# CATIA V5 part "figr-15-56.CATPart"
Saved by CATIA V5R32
Part number: Part1
Bounding box of the stored display mesh (mm): x -75 to -29.087, y -20 to 20, z 0 to 62.461
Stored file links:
  D:\PROJECTS\Project 2022\CATIA V5 6R 2022\Resources\Part Files\c15_catia_v5_6r2022_prt\figr-15-56.CATPart
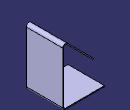
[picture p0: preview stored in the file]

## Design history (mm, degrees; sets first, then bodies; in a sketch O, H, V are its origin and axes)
SheetMetalParameters1: Thickness 1, BendRadius 2, KFactor 0.400515 {= log(min(100,max(20*SheetMetalParameters1.BendRadius,SheetMetalParameters1.Thickness)/SheetMetalParameters1.Thickness))/log(100)/2}, ReliefRadialLength 1, ReliefAxialLength 2, MinimumBendRadius 0
Body1 (main body)
  Sketch1 on xy-plane, origin (0, 0, 0), H (1, 0, 0), V (0, 1, 0)
    line L1 (-75, 20) -> (75, 20)
    line L2 (75, 20) -> (75, -20)
    line L3 (75, -20) -> (-75, -20)
    line L4 (-75, -20) -> (-75, 20)
    distance L1 L3 = 40
    distance L2 L4 = 150
    distance V L2 = 75
    distance H L3 = 20
    horizontal: L1 H, L3 H
    vertical: L2 V, L4 V
  Wall1: Thickness 1, Profile Sketch1
  Sketch2 on face of Wall1, origin (0, 0, 1), H (1, 0, 0), V (0, 1, 0)
    line L1 (-30.2021, 19.5432) -> (-30.2021, -20.6466)
    line L2 (31.0296, 19.5432) -> (31.0296, -20.6466)
    vertical: L1 V, L2 V
  FlatBend1: FlatBendAngle 90, FlatBendAngle 45, Axis Sketch2, FixedPoint vertex [face of Wall1 | face of Wall1 | face of Wall1], FlatBendKFactor 0.400515 {= log(min(100,max(20*FlatBend1.FlatBendRadius,SheetMetalParameters1.Thickness)/SheetMetalParameters1.Thickness))/log(100)/2}, FlatBendKFactor 0.400515 {= log(min(100,max(20*FlatBend1.FlatBendRadius,SheetMetalParameters1.Thickness)/SheetMetalParameters1.Thickness))/log(100)/2}, FlatBendRadius 2 {= SheetMetalParameters1.BendRadius}, FlatBendRadius 2 {= SheetMetalParameters1.BendRadius}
